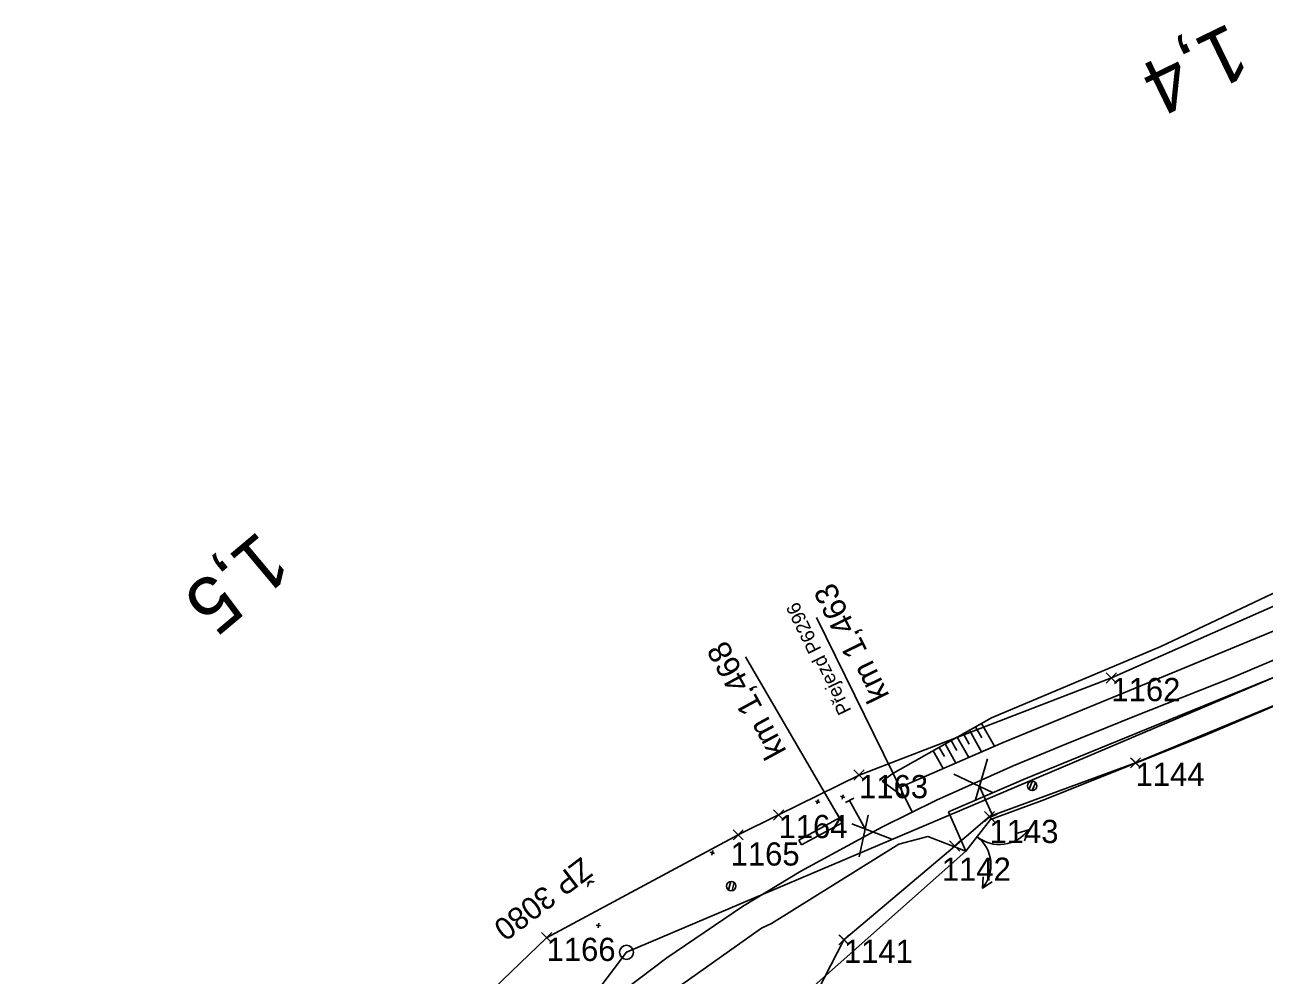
# Model space of a CAD drawing. Extents: x -738085 to -734426, y -1122197 to -1119748.
# Drawn here: x -735466.6 to -735333, y -1120405.2 to -1120302.7 of the extents above; entities that cross this region are included whole.
import ezdxf

# ---------------------------------------------------------------- set-up
doc = ezdxf.new("R2010")
doc.units = 0
for name, color, linetype in [('SŽDC', 7, 'Continuous'), ('Vrstva 1', 7, 'Continuous'), ('Vrstva 11', 7, 'Continuous'), ('Vrstva 17', 7, 'Continuous'), ('Vrstva 4', 7, 'Continuous'), ('Vrstva 48', 7, 'Continuous'), ('Vrstva 49', 7, 'Continuous'), ('Vrstva 60', 7, 'Continuous'), ('Vrstva 63', 7, 'Continuous'), ('Vrstva 7', 7, 'Continuous'), ('Vrstva 9', 7, 'Continuous')]:
    doc.layers.add(name, color=color, linetype=linetype)

msp = doc.modelspace()

# ---------------------------------------------------------------- linework, layer by layer
at = {"layer": 'SŽDC'}
for p, q in [((-735322.23, -1120372.05), (-735346.89, -1120382.27)), ((-735346.89, -1120382.27), (-735362.63, -1120388.07)), ((-735385.37, -1120387.89), (-735376.69, -1120383.59)), ((-735389.72, -1120390.04), (-735385.37, -1120387.89)), ((-735362.63, -1120388.07), (-735366.38, -1120391.25)), ((-735410.38, -1120401.13), (-735389.72, -1120390.04)), ((-735366.38, -1120391.25), (-735378.33, -1120401.35)), ((-735417.02, -1120407.52), (-735410.38, -1120401.13)), ((-735378.33, -1120401.35), (-735382.4, -1120409.22))]:
    msp.add_line(p, q, dxfattribs=at)
msp.add_lwpolyline([(-735376.69, -1120383.59), (-735349.49, -1120373.13), (-735311.53, -1120356.35), (-735287.65, -1120341.7), (-735286.9, -1120333.84)], dxfattribs=at)
at = {"layer": 'Vrstva 1'}
msp.add_lwpolyline([(-735304.06, -1120357.75), (-735312.6, -1120362.28), (-735321.76, -1120366.74), (-735327.51, -1120369.32), (-735336.44, -1120373.09), (-735346.98, -1120377.26), (-735354.33, -1120380.21), (-735360.07, -1120382.6), (-735368.33, -1120386.31), (-735374.16, -1120389.16), (-735382.98, -1120393.95), (-735389.27, -1120397.76), (-735397.43, -1120403.28), (-735404.93, -1120408.97)], dxfattribs=at)
msp.add_lwpolyline([(-735304.06, -1120357.75), (-735312.6, -1120362.28), (-735321.76, -1120366.74), (-735327.51, -1120369.32), (-735336.44, -1120373.09), (-735346.98, -1120377.26), (-735354.33, -1120380.21), (-735360.07, -1120382.6), (-735368.33, -1120386.31), (-735374.16, -1120389.16), (-735382.98, -1120393.95), (-735389.27, -1120397.76), (-735397.43, -1120403.28), (-735404.93, -1120408.97)], dxfattribs=at)
at = {"layer": 'Vrstva 11'}
for p, q in [((-735358.02, -1120384.27), (-735358.37, -1120385.12)), ((-735357.67, -1120384.42), (-735358.02, -1120385.26)), ((-735390.53, -1120395.06), (-735390.75, -1120395.96)), ((-735390.17, -1120395.16), (-735390.39, -1120396.05))]:
    msp.add_line(p, q, dxfattribs=at)
for centre in [(-735358.03, -1120384.76), (-735390.47, -1120395.56)]:
    msp.add_circle(centre, 0.5, dxfattribs=at)
at = {"layer": 'Vrstva 17'}
for points in [[(-735365.2, -1120391.78), (-735362.53, -1120388.38), (-735356.97, -1120386.34), (-735339.6, -1120379.39), (-735326.23, -1120373.72), (-735309.96, -1120366.69), (-735292.76, -1120357.85), (-735282.13, -1120352.28)], [(-735358.87, -1120390.68), (-735358.44, -1120389.49), (-735359.61, -1120389.85)], [(-735462.33, -1120520.63), (-735452.42, -1120489.18), (-735439.43, -1120465.73), (-735427.21, -1120446.84), (-735400.53, -1120421.04), (-735389.5, -1120413.38), (-735365.2, -1120391.78)], [(-735362.33, -1120395.09), (-735363.39, -1120395.78), (-735363.32, -1120394.56)]]:
    msp.add_lwpolyline(points, dxfattribs=at)
for centre, start, end in [((-735361.56, -1120387.26), 230.8103, 324.3302), ((-735366.3, -1120393.29), 319.3598, 52.8797)]:
    msp.add_arc(centre, 3.83, start, end, dxfattribs=at)
at = {"layer": 'Vrstva 4'}
for p, q in [((-735381.27, -1120366.6), (-735370.98, -1120387.6)), ((-735364.14, -1120386.28), (-735362.84, -1120381.86)), ((-735366.49, -1120383.5), (-735362.32, -1120385.46)), ((-735362.27, -1120388.02), (-735363.7, -1120384.82)), ((-735377.27, -1120386.08), (-735378.15, -1120386.55)), ((-735377.71, -1120386.32), (-735376.04, -1120389.39)), ((-735374.16, -1120389.16), (-735368.33, -1120386.31)), ((-735373.16, -1120390.5), (-735377.46, -1120388.86)), ((-735375.71, -1120387.9), (-735376.67, -1120392.41)), ((-735362.73, -1120388.22), (-735361.81, -1120387.81))]:
    msp.add_line(p, q, dxfattribs=at)
at = {"layer": 'Vrstva 48'}
for p, q in [((-735364.14, -1120378.4), (-735363.47, -1120379.59)), ((-735363.49, -1120378.03), (-735362.1, -1120380.49)), ((-735366.1, -1120379.51), (-735364.86, -1120381.7)), ((-735365.45, -1120379.14), (-735364.81, -1120380.26)), ((-735364.8, -1120378.77), (-735363.48, -1120381.09)), ((-735368.71, -1120380.98), (-735367.63, -1120382.9)), ((-735368.06, -1120380.61), (-735367.5, -1120381.61)), ((-735367.41, -1120380.24), (-735366.25, -1120382.3)), ((-735366.76, -1120379.87), (-735366.16, -1120380.94))]:
    msp.add_line(p, q, dxfattribs=at)
at = {"layer": 'Vrstva 49'}
for p, q in [((-735330.81, -1120363.42), (-735344.17, -1120369.73)), ((-735344.17, -1120369.73), (-735362.4, -1120377.41)), ((-735340.77, -1120376.64), (-735327.45, -1120371.2)), ((-735358.7, -1120383.97), (-735340.77, -1120376.64)), ((-735362.4, -1120377.41), (-735373.04, -1120383.43)), ((-735373.04, -1120383.43), (-735374.2, -1120384.26)), ((-735374.2, -1120384.26), (-735372.06, -1120385.82)), ((-735367.06, -1120387.57), (-735358.7, -1120383.97)), ((-735380.91, -1120386.54), (-735381.39, -1120386.4)), ((-735381.08, -1120386.23), (-735381.23, -1120386.71)), ((-735378.22, -1120386.03), (-735378.7, -1120385.88)), ((-735378.39, -1120385.71), (-735378.53, -1120386.19)), ((-735367.06, -1120387.57), (-735365.2, -1120391.78)), ((-735392.46, -1120391.74), (-735392.58, -1120392.22)), ((-735392.28, -1120392.04), (-735392.76, -1120391.92)), ((-735404.55, -1120399.84), (-735405.05, -1120399.78)), ((-735404.76, -1120399.56), (-735404.83, -1120400.06))]:
    msp.add_line(p, q, dxfattribs=at)
for points in [[(-735372.06, -1120385.82), (-735372.14, -1120384.88), (-735361.16, -1120380.07), (-735342.64, -1120372.48), (-735329.16, -1120366.91), (-735313.94, -1120359.68), (-735296.66, -1120349.91), (-735282.53, -1120341.71), (-735274.84, -1120337.93)], [(-735272.37, -1120342.05), (-735277.85, -1120346.97), (-735282.13, -1120352.28), (-735292.76, -1120357.85), (-735309.96, -1120366.69), (-735326.23, -1120373.72), (-735339.6, -1120379.39), (-735356.97, -1120386.34), (-735362.53, -1120388.38), (-735365.2, -1120391.78)], [(-735468.93, -1120523.64), (-735468.12, -1120518.62), (-735465.32, -1120504.82), (-735460.36, -1120489.68), (-735454.87, -1120475.59), (-735447.25, -1120462.5), (-735437.92, -1120447.04), (-735425.14, -1120430.75), (-735414.69, -1120420.37), (-735398.43, -1120408.02), (-735387.2, -1120400.09), (-735386.13, -1120399.6), (-735372.42, -1120391.06), (-735369.29, -1120390.2), (-735365.2, -1120391.78)], [(-735365.2, -1120391.78), (-735389.5, -1120413.38), (-735400.53, -1120421.04), (-735429.12, -1120446.55), (-735441.7, -1120464.87), (-735453.7, -1120488.3), (-735461.11, -1120511.02), (-735461.11, -1120511.11)]]:
    msp.add_lwpolyline(points, dxfattribs=at)
at = {"layer": 'Vrstva 60'}
for p, q in [((-735349.04, -1120373.58), (-735350.04, -1120372.58)), ((-735349.04, -1120372.68), (-735350.04, -1120373.68)), ((-735349.94, -1120373.58), (-735348.94, -1120372.58)), ((-735349.94, -1120372.68), (-735348.94, -1120373.68)), ((-735349.49, -1120373.13), (-735349.49, -1120373.13)), ((-735346.44, -1120382.72), (-735347.44, -1120381.72)), ((-735346.44, -1120381.82), (-735347.44, -1120382.82)), ((-735347.34, -1120382.72), (-735346.34, -1120381.72)), ((-735347.34, -1120381.82), (-735346.34, -1120382.82)), ((-735346.89, -1120382.27), (-735346.89, -1120382.27)), ((-735376.24, -1120384.04), (-735377.24, -1120383.04)), ((-735376.24, -1120383.14), (-735377.24, -1120384.14)), ((-735377.14, -1120384.04), (-735376.14, -1120383.04)), ((-735377.14, -1120383.14), (-735376.14, -1120384.14)), ((-735376.69, -1120383.59), (-735376.69, -1120383.59)), ((-735384.92, -1120388.34), (-735385.92, -1120387.34)), ((-735384.92, -1120387.44), (-735385.92, -1120388.44)), ((-735385.82, -1120388.34), (-735384.82, -1120387.34)), ((-735385.82, -1120387.44), (-735384.82, -1120388.44)), ((-735362.18, -1120388.52), (-735363.18, -1120387.52)), ((-735362.18, -1120387.62), (-735363.18, -1120388.62)), ((-735363.08, -1120388.52), (-735362.08, -1120387.52)), ((-735363.08, -1120387.62), (-735362.08, -1120388.62)), ((-735385.37, -1120387.89), (-735385.37, -1120387.89)), ((-735362.63, -1120388.07), (-735362.63, -1120388.07)), ((-735389.27, -1120390.49), (-735390.27, -1120389.49)), ((-735389.27, -1120389.59), (-735390.27, -1120390.59)), ((-735390.17, -1120390.49), (-735389.17, -1120389.49)), ((-735390.17, -1120389.59), (-735389.17, -1120390.59)), ((-735389.72, -1120390.04), (-735389.72, -1120390.04)), ((-735365.93, -1120391.7), (-735366.93, -1120390.7)), ((-735365.93, -1120390.8), (-735366.93, -1120391.8)), ((-735366.83, -1120391.7), (-735365.83, -1120390.7)), ((-735366.83, -1120390.8), (-735365.83, -1120391.8)), ((-735366.38, -1120391.25), (-735366.38, -1120391.25)), ((-735409.93, -1120401.58), (-735410.93, -1120400.58)), ((-735409.93, -1120400.68), (-735410.93, -1120401.68)), ((-735410.83, -1120401.58), (-735409.83, -1120400.58)), ((-735410.83, -1120400.68), (-735409.83, -1120401.68)), ((-735377.88, -1120401.8), (-735378.88, -1120400.8)), ((-735377.88, -1120400.9), (-735378.88, -1120401.9)), ((-735378.78, -1120401.8), (-735377.78, -1120400.8)), ((-735378.78, -1120400.9), (-735377.78, -1120401.9)), ((-735410.38, -1120401.13), (-735410.38, -1120401.13)), ((-735378.33, -1120401.35), (-735378.33, -1120401.35))]:
    msp.add_line(p, q, dxfattribs=at)
at = {"layer": 'Vrstva 63'}
for p, q in [((-735401.76, -1120402.7), (-735310.08, -1120363.77)), ((-735464.41, -1120485.08), (-735401.76, -1120402.7)), ((-735401.72, -1120402.67), (-735401.8, -1120402.73))]:
    msp.add_line(p, q, dxfattribs=at)
msp.add_circle((-735401.76, -1120402.7), 0.756, dxfattribs=at)
at = {"layer": 'Vrstva 9'}
for p, q in [((-735378.65, -1120388.48), (-735388.95, -1120370.86)), ((-735378.79, -1120388.22), (-735379.08, -1120387.69)), ((-735378.79, -1120388.22), (-735383.19, -1120390.6)), ((-735382.9, -1120391.13), (-735378.5, -1120388.74)), ((-735378.5, -1120388.74), (-735378.79, -1120388.22)), ((-735383.19, -1120390.6), (-735382.9, -1120391.13))]:
    msp.add_line(p, q, dxfattribs=at)

# ---------------------------------------------------------------- texts
at = {"layer": 'Vrstva 4'}
for s, height, p in [('km 1,463', 2.5, (-735373.38, -1120375.04)), ('Přejezd P6296', 1.5, (-735377.49, -1120376.64))]:
    msp.add_text(s, height=height, rotation=116.1032, dxfattribs=at).set_placement(p)
at = {"layer": 'Vrstva 60'}
for s, p in [('1162', (-735349.49, -1120375.63)), ('1144', (-735346.89, -1120384.77)), ('1163', (-735376.69, -1120386.09)), ('1164', (-735385.37, -1120390.39)), ('1143', (-735362.63, -1120390.92)), ('1165', (-735390.54, -1120393.35)), ('1142', (-735367.77, -1120394.99)), ('1166', (-735410.38, -1120403.63)), ('1141', (-735378.33, -1120403.85))]:
    msp.add_text(s, height=2.5, dxfattribs=at).set_placement(p)
at = {"layer": 'Vrstva 63'}
msp.add_text('ŽP 3080', height=2.4, rotation=217.2106, dxfattribs=at).set_placement((-735406.62, -1120392.35))
at = {"layer": 'Vrstva 7'}
for s, rotation, p in [('1,4', 205.9461, (-735336.73, -1120302.46)), ('1,4', 205.9461, (-735336.73, -1120302.46)), ('1,5', 219.9701, (-735441.35, -1120357.12)), ('1,5', 219.9701, (-735441.35, -1120357.12))]:
    msp.add_text(s, height=6, rotation=rotation, dxfattribs=at).set_placement(p)
at = {"layer": 'Vrstva 9'}
msp.add_text('km 1,468', height=2.5, rotation=118.4842, dxfattribs=at).set_placement((-735384.46, -1120381.02))

doc.saveas('drawing.dxf')
